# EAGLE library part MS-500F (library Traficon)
DPDT - TOGGLE SWITCH Manufacturer: Miyama Rating: 6A/125VAC Distributor: D'Tron
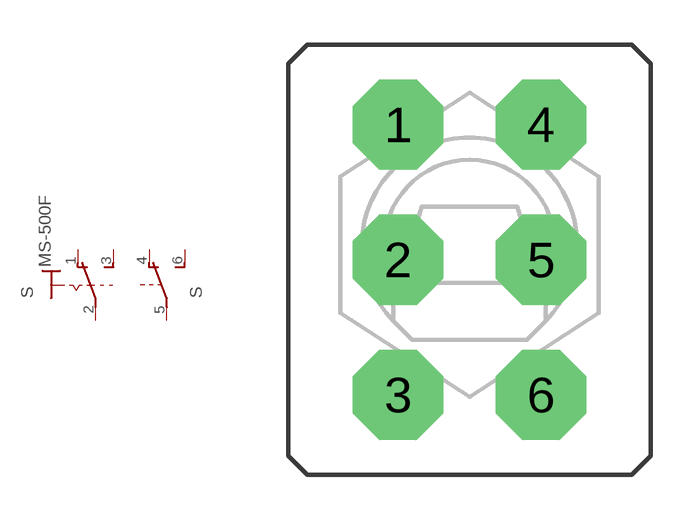
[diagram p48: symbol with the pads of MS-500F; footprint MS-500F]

Designator prefix S; gates B=U2 1=KS-U-

## MS-500F  [MS-500F]
1  1:1  pas
2  1:P  pas
3  1:3  pas
4  B:O  pas
5  B:P  pas
6  B:S  pas

## Footprint MS-500F (pad centres in mm)
TOGGLE SWITCH distributor RS Components
drill 2.007 octagon: 1 -2.388,4.013; 2 -2.388,-0.5; 3 -2.388,-5.013; 4 2.388,4.013; 5 2.388,-0.5; 6 2.388,-5.013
